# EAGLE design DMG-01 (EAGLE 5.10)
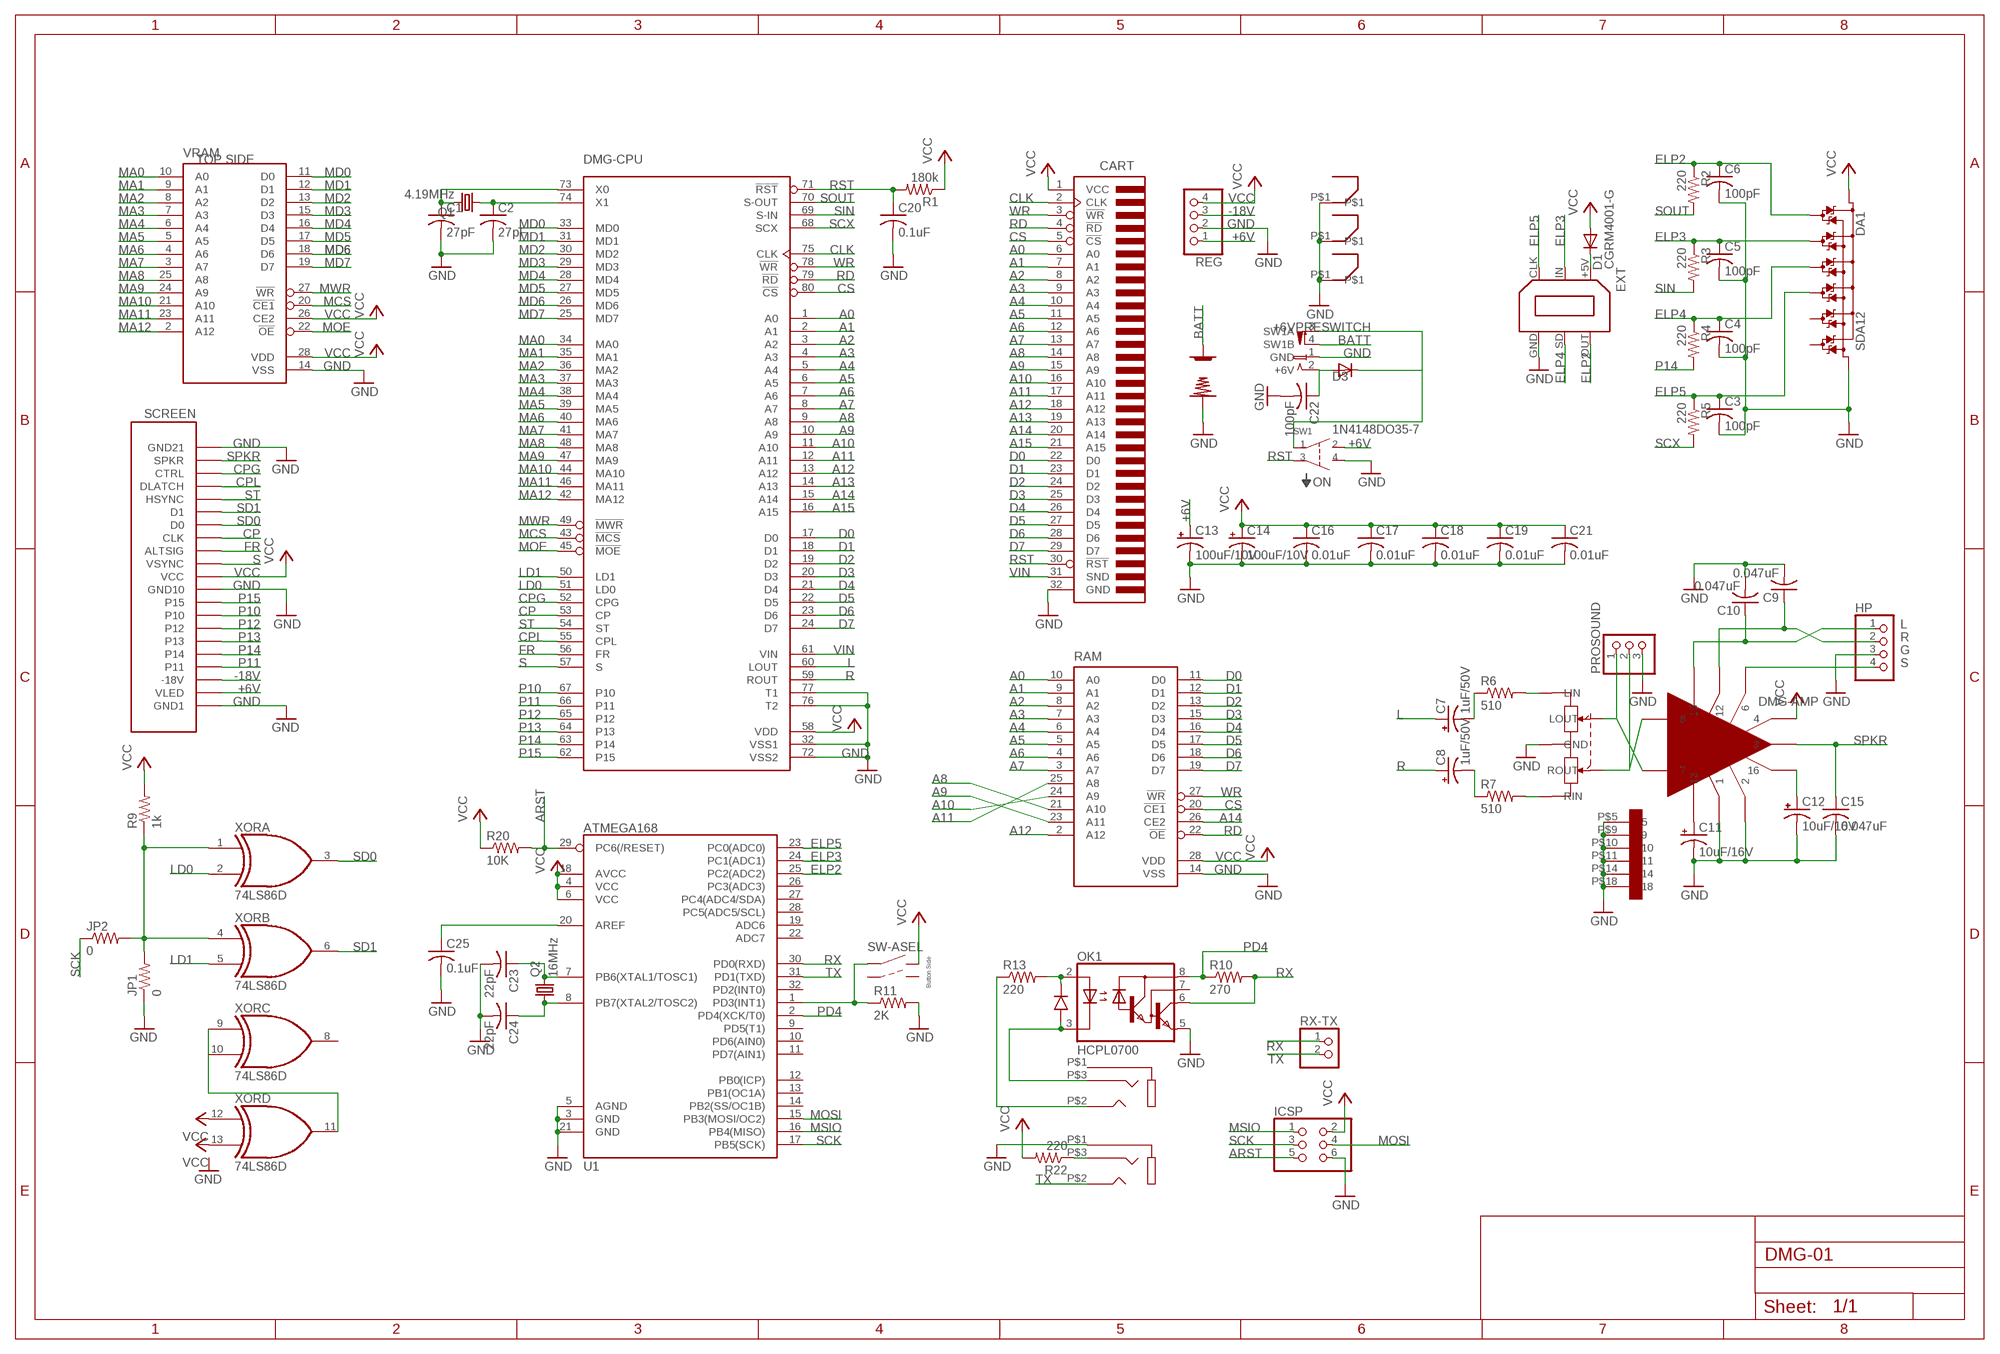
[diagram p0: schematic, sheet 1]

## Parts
+  DMG+BATTERY  [DMG+BATTERY]
-  DMG-BATTERY  [DMG-BATTERY]
C1  27pF  C0603  [R0603]
C2  27pF  C0603  [R0603]
C3  100pF  C0603  [R0603]
C4  100pF  C0603  [R0603]
C5  100pF  C0603  [R0603]
C6  100pF  C0603  [R0603]
C7  1uF/50V  C1206  [C1206]
C8  1uF/50V  C1206  [C1206]
C9  0.047uF  C0603  [R0603]
C10  0.047uF  C0603  [R0603]
C11  10uF/16V  C1206  [C1206]
C12  10uF/16V  C1206  [C1206]
C13  100uF/10V  C1206  [C1206]
C14  100uF/10V  C1206  [C1206]
C15  0.047uF  C0603  [R0603]
C16  0.01uF  C0603  [R0603]
C17  0.01uF  C0603  [R0603]
C18  0.01uF  C0603  [R0603]
C19  0.01uF  C0603  [R0603]
C20  0.1uF  C0603  [R0603]
C21  0.01uF  C0603  [R0603]
C22  100pF  C0603  [R0603]
C23  22pF  C0603  [R0603]
C24  22pF  C0603  [R0603]
C25  0.1uF  C0603  [R0603]
CART  GBCONN  [GBCONN]
D1  CGRM4001-G  [SOD-123_MINI-SMA]
D2  1N914  [SC-79]
D3  1N4148DO35-7  [DO35-7]
DA1  SDA12  [SO8]
DMG-AMP  DMG-AMP  [DMG-AMP]
DMG-CPU  DMG-CPU  [DMG-CPU]
EXT  LINKPORTDMG-LINK-SHORT  LINKPORTDMG-LINK  [DMG-LINK]
HP  PINHD-1X4OCT  [1X04OCT]
ICSP  PINHD-2X3  [2X03]
JP1  0  R0603  [R0603]
JP2  0  R0603  [R0603]
MIDIIN  SJ-3523  [SJ-3523]
MIDIOUT  SJ-3523  [SJ-3523]
OK1  HCPL0700  [SOIC08]
PROSOUND  PINHD-1X3OCT  [1X03OCT]
PWRJACK  DMG-PWRJACK  [DMG-PWRJACK]
Q1  4.19MHz  CRYSTALHC49S  [HC49/S]
Q2  16MHz  CRYSTALCTS406  [CTS406]
R1  180k  R0603  [R0603]
R2  220  R0603  [R0603]
R3  220  R0603  [R0603]
R4  220  R0603  [R0603]
R5  220  R0603  [R0603]
R6  510  R0603  [R0603]
R7  510  R0603  [R0603]
R9  1k  R0603  [R0603]
R10  270  R0603  [R0603]
R11  2K  R0603  [R0603]
R13  220  R0603  [R0603]
R20  10K  R0603  [R0603]
R22  220  R0603  [R0603]
RAM  LH5264  [SO28]
REG  PINHD-1X4OCT  [1X04OCT]
RX-TX  PINHD-1X2OCT  [1X02OCT]
SCREEN  DMG-SCREEN  DMG-SCREENCONNECTOR  [DMG-SCREEN]
SW1  DMG-SW  [DMG-SWITCH]
SW-ASEL  EVQ-PU  EVQ-PUNOGUIDE  [EVQ-PU2]
U1  ATMEGA168  [TQFP32-08]
U$1  DMG-CONTACT  [DMG-CONTACT]
U$2  DMG-CONTACT  [DMG-CONTACT]
U$3  DMG-CONTACT  [DMG-CONTACT]
VR1  10K  DMG-POT  [DMG-POT]
VRAM  LH5264  [SO28]
XOR  74LS86D  [SO14]

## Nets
+6V: C13.+ REG.1 SCREEN.P$2(VLED) SW1.P$2
+6VEXT: C22.1 D3.A PWRJACK.2(+6V)
+6VPRESWITCH: D3.C PWRJACK.3(SW1A) SW1.P$1
-18V: REG.3 SCREEN.P$3(-18V)
A0: CART.6(A0) DMG-CPU.1(A0) RAM.10(A0)
A1: CART.7(A1) DMG-CPU.2(A1) RAM.9(A1)
A2: CART.8(A2) DMG-CPU.3(A2) RAM.8(A2)
A3: CART.9(A3) DMG-CPU.4(A3) RAM.7(A3)
A4: CART.10(A4) DMG-CPU.5(A4) RAM.6(A4)
A5: CART.11(A5) DMG-CPU.6(A5) RAM.5(A5)
A6: CART.12(A6) DMG-CPU.7(A6) RAM.4(A6)
A7: CART.13(A7) DMG-CPU.8(A7) RAM.3(A7)
A8: CART.14(A8) DMG-CPU.9(A8) RAM.21(A10)
A9: CART.15(A9) DMG-CPU.10(A9) RAM.23(A11)
A10: CART.16(A10) DMG-CPU.11(A10) RAM.24(A9)
A11: CART.17(A11) DMG-CPU.12(A11) RAM.25(A8)
A12: CART.18(A12) DMG-CPU.13(A12) RAM.2(A12)
A13: CART.19(A13) DMG-CPU.14(A13)
A14: CART.20(A14) DMG-CPU.15(A14) RAM.26(CE2)
A15: CART.21(A15) DMG-CPU.16(A15)
ARST: ICSP.5 R20.2 U1.29(PC6(/RESET))
BATT: +.P$1 PWRJACK.4(SW1B)
CLK: CART.2(CLK) DMG-CPU.75(CLK)
CP: DMG-CPU.53(CP) SCREEN.P$14(CLK)
CPG: DMG-CPU.52(CPG) SCREEN.P$19(CTRL)
CPL: DMG-CPU.55(CPL) SCREEN.P$18(DLATCH)
CS: CART.5(!CS) DMG-CPU.80(!CS) RAM.20(!CE1)
D0: CART.22(D0) DMG-CPU.17(D0) RAM.11(D0)
D1: CART.23(D1) DMG-CPU.18(D1) RAM.12(D1)
D2: CART.24(D2) DMG-CPU.19(D2) RAM.13(D2)
D3: CART.25(D3) DMG-CPU.20(D3) RAM.15(D3)
D4: CART.26(D4) DMG-CPU.21(D4) RAM.16(D4)
D5: CART.27(D5) DMG-CPU.22(D5) RAM.17(D5)
D6: CART.28(D6) DMG-CPU.23(D6) RAM.18(D6)
D7: CART.29(D7) DMG-CPU.24(D7) RAM.19(D7)
ELP2: C6.1 DA1.2(D01) EXT.OUT R2.1 U1.25(PC2(ADC2))
ELP3: C5.1 DA1.3(D02) EXT.IN R3.1 U1.24(PC1(ADC1))
ELP4: C4.1 DA1.4(D03) EXT.SD R4.1
ELP5: C3.1 DA1.6(D04) EXT.CLK R5.1 U1.23(PC0(ADC0))
FR: DMG-CPU.56(FR) SCREEN.P$13(ALTSIG)
GND: -.P$1 C1.2 C2.2 C3.2 C4.2 C5.2 C6.2 C9.2 C10.2 C11.- C12.- C13.- C14.- C15.2 C16.2 C17.2 C18.2 C19.2 C20.2 C21.2 C22.2 C23.2 C24.2 C25.2 CART.32(GND) DA1.5(V-) DMG-AMP.P$1 DMG-AMP.P$2 DMG-AMP.P$5 DMG-AMP.P$9 DMG-AMP.P$10 DMG-AMP.P$11 DMG-AMP.P$14 DMG-AMP.P$18 DMG-CPU.32(VSS1) DMG-CPU.72(VSS2) DMG-CPU.76(T2) DMG-CPU.77(T1) EXT.GND HP.3 ICSP.6 JP1.1 MIDIOUT.P$1 OK1.5(GND) PROSOUND.3 PWRJACK.1(GND) R11.2 RAM.14(VSS) REG.2 SCREEN.P$1(GND1) SCREEN.P$10(GND10) SCREEN.P$21(GND21) SW1.P$4 U1.3(GND) U1.5(AGND) U1.21(GND) U$1.P$1 U$2.P$1 U$3.P$1 VR1.P$1(GND) VRAM.14(VSS)
L: C7.+ DMG-CPU.60(LOUT)
LD0: DMG-CPU.51(LD0) XOR.2(A:I1)
LD1: DMG-CPU.50(LD1) XOR.5(B:I1)
MA0: DMG-CPU.34(MA0) VRAM.10(A0)
MA1: DMG-CPU.35(MA1) VRAM.9(A1)
MA2: DMG-CPU.36(MA2) VRAM.8(A2)
MA3: DMG-CPU.37(MA3) VRAM.7(A3)
MA4: DMG-CPU.38(MA4) VRAM.6(A4)
MA5: DMG-CPU.39(MA5) VRAM.5(A5)
MA6: DMG-CPU.40(MA6) VRAM.4(A6)
MA7: DMG-CPU.41(MA7) VRAM.3(A7)
MA8: DMG-CPU.48(MA8) VRAM.25(A8)
MA9: DMG-CPU.47(MA9) VRAM.24(A9)
MA10: DMG-CPU.44(MA10) VRAM.21(A10)
MA11: DMG-CPU.46(MA11) VRAM.23(A11)
MA12: DMG-CPU.42(MA12) VRAM.2(A12)
MCS: DMG-CPU.43(!MCS) VRAM.20(!CE1)
MD0: DMG-CPU.33(MD0) VRAM.11(D0)
MD1: DMG-CPU.31(MD1) VRAM.12(D1)
MD2: DMG-CPU.30(MD2) VRAM.13(D2)
MD3: DMG-CPU.29(MD3) VRAM.15(D3)
MD4: DMG-CPU.28(MD4) VRAM.16(D4)
MD5: DMG-CPU.27(MD5) VRAM.17(D5)
MD6: DMG-CPU.26(MD6) VRAM.18(D6)
MD7: DMG-CPU.25(MD7) VRAM.19(D7)
MOE: DMG-CPU.45(!MOE) VRAM.22(!OE)
MOSI: ICSP.4 U1.15(PB3(MOSI/OC2))
MSIO: ICSP.1 U1.16(PB4(MISO))
MWR: DMG-CPU.49(!MWR) VRAM.27(!WR)
N$1: C11.+ DMG-AMP.P$13
N$2: C12.+ DMG-AMP.P$16
N$3: C10.1 DMG-AMP.P$15 HP.1
N$4: XOR.9(C:I0) XOR.10(C:I1) XOR.11(D:O)
N$10: JP1.2 JP2.2 R9.1 XOR.1(A:I0) XOR.4(B:I0)
N$13: R11.1 SW-ASEL.P$1 U1.1(PD3(INT1))
N$17: D1.C EXT.+5V
N$19: R6.2 VR1.P$4(LIN)
N$20: R7.2 VR1.P$5(RIN)
N$21: C7.- R6.1
N$22: C8.- R7.1
N$23: DMG-AMP.P$7 PROSOUND.1 VR1.P$3(LOUT)
N$24: DMG-AMP.P$8 PROSOUND.2 VR1.P$2(ROUT)
N$26: C9.1 DMG-AMP.P$12 HP.2
N$27: MIDIIN.P$2 R13.1
N$28: DMG-AMP.P$6 HP.4
N$31: D2.P$1 OK1.2(A) R13.2
N$32: C25.1 U1.20(AREF)
N$36: C23.1 Q2.3 U1.7(PB6(XTAL1/TOSC1))
N$37: C24.1 Q2.1 U1.8(PB7(XTAL2/TOSC2))
N$38: D2.P$2 MIDIIN.P$3 OK1.3(C)
N$40: MIDIOUT.P$3 R22.1
P10: DMG-CPU.67(P10) SCREEN.P$8(P10)
P11: DMG-CPU.66(P11) SCREEN.P$4(P11)
P12: DMG-CPU.65(P12) SCREEN.P$7(P12)
P13: DMG-CPU.64(P13) SCREEN.P$6(P13)
P14: DMG-CPU.63(P14) R4.2 SCREEN.P$5(P14)
P15: DMG-CPU.62(P15) SCREEN.P$9(P15)
PD4: OK1.8(VCC) R10.1 U1.2(PD4(XCK/T0))
R: C8.+ DMG-CPU.59(ROUT)
RD: CART.4(!RD) DMG-CPU.79(!RD) RAM.22(!OE)
RST: C20.1 CART.30(!RST) DMG-CPU.71(!RST) R1.2 SW1.P$3
RX: OK1.6(VO) R10.2 RX-TX.1 U1.30(PD0(RXD))
S: DMG-CPU.57(S) SCREEN.P$12(VSYNC)
SCK: ICSP.3 JP2.1 U1.17(PB5(SCK))
SCX: DMG-CPU.68(SCX) R5.2
SD0: SCREEN.P$15(D0) XOR.3(A:O)
SD1: SCREEN.P$16(D1) XOR.6(B:O)
SIN: DMG-CPU.69(S-IN) R3.2
SOUT: DMG-CPU.70(S-OUT) R2.2
SPKR: C15.1 DMG-AMP.P$3 SCREEN.P$20(SPKR)
ST: DMG-CPU.54(ST) SCREEN.P$17(HSYNC)
TX: MIDIOUT.P$2 RX-TX.2 U1.31(PD1(TXD))
VCC: C14.+ C16.1 C17.1 C18.1 C19.1 C21.1 CART.1(VCC) D1.A DA1.1(V+) DMG-AMP.P$4 DMG-CPU.58(VDD) ICSP.2 R1.1 R9.2 R20.1 R22.2 RAM.28(VDD) REG.4 SCREEN.P$11(VCC) SW-ASEL.P$2 U1.4(VCC) U1.6(VCC) U1.18(AVCC) VRAM.26(CE2) VRAM.28(VDD) XOR.12(D:I0) XOR.13(D:I1)
VIN: CART.31(SND) DMG-CPU.61(VIN)
WR: CART.3(!WR) DMG-CPU.78(!WR) RAM.27(!WR)
X0: C1.1 DMG-CPU.73(X0) Q1.2
X1: C2.1 DMG-CPU.74(X1) Q1.1
Unconnected: DA1.7(D05) DA1.8(D06) MIDIIN.P$1 OK1.7(VB) SW-ASEL.P$3 SW-ASEL.P$4 U1.9(PD5(T1)) U1.10(PD6(AIN0)) U1.11(PD7(AIN1)) U1.12(PB0(ICP)) U1.13(PB1(OC1A)) U1.14(PB2(SS/OC1B)) U1.19(ADC6) U1.22(ADC7) U1.26(PC3(ADC3)) U1.27(PC4(ADC4/SDA)) U1.28(PC5(ADC5/SCL)) U1.32(PD2(INT0)) XOR.8(C:O)

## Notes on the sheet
- TOP SIDE
- L
- R
- G
- S

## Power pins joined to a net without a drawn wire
GND: XOR.7(P:GND)
VCC: XOR.14(P:VCC)

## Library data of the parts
+ = Game Boy:DMG+BATTERY
- = Game Boy:DMG-BATTERY
C1-C6 C9 C10 C15-C25 = Game Boy:C0603
C7 C8 C11-C14 = Game Boy:C1206
CART = GameboyDev:GBCONN
D1 = diode:CGRM400*-G: Molded plasitc,JEDEC SOD-123/Mini SMA
D2 = Game Boy:1N914
D3 = diode:1N4148: DIODE
DA1 = zetex:SDA12: DIODE ARRAY
DMG-AMP = Game Boy:DMG-AMP
DMG-CPU = Game Boy:DMG-CPU
EXT = Game Boy:LINKPORT
HP REG = pinhead:PINHD-1X4: PIN HEADER
ICSP = pinhead:PINHD-2X3: PIN HEADER
JP1 JP2 R1-R7 R9-R11 R13 R20 R22 = Game Boy:R0603
MIDIIN MIDIOUT = Game Boy:SJ-3523
OK1 = optocoupler:HCPL0700: HEWLETT PACKARD OPTO COUPLER
PROSOUND = header:PINHD-1X3: PIN HEADER
PWRJACK = Game Boy:DMG-PWRJACK
Q1 Q2 = crystal:CRYSTAL: CRYSTAL
RAM VRAM = Game Boy:LH5264
RX-TX = pinhead:PINHD-1X2: PIN HEADER
SCREEN = Game Boy:DMG-SCREEN: The white connector for the ribbon cable to connect the DMG's front half
SW1 = Game Boy:DMG-SW: DMG Power Switch Pins 1 and 2 are only connected when the power is ON, pins 3 and 4 are only connected when the power is OFF.
SW-ASEL = Game Boy:EVQ-PU
U1 = SparkFun:ATMEGA168
U$1-U$3 = Game Boy:DMG-CONTACT
VR1 = Game Boy:DMG-POT
XOR = 74xx-us:74*86: Quad 2-input EXCLUSIV-OR (XOR) gate

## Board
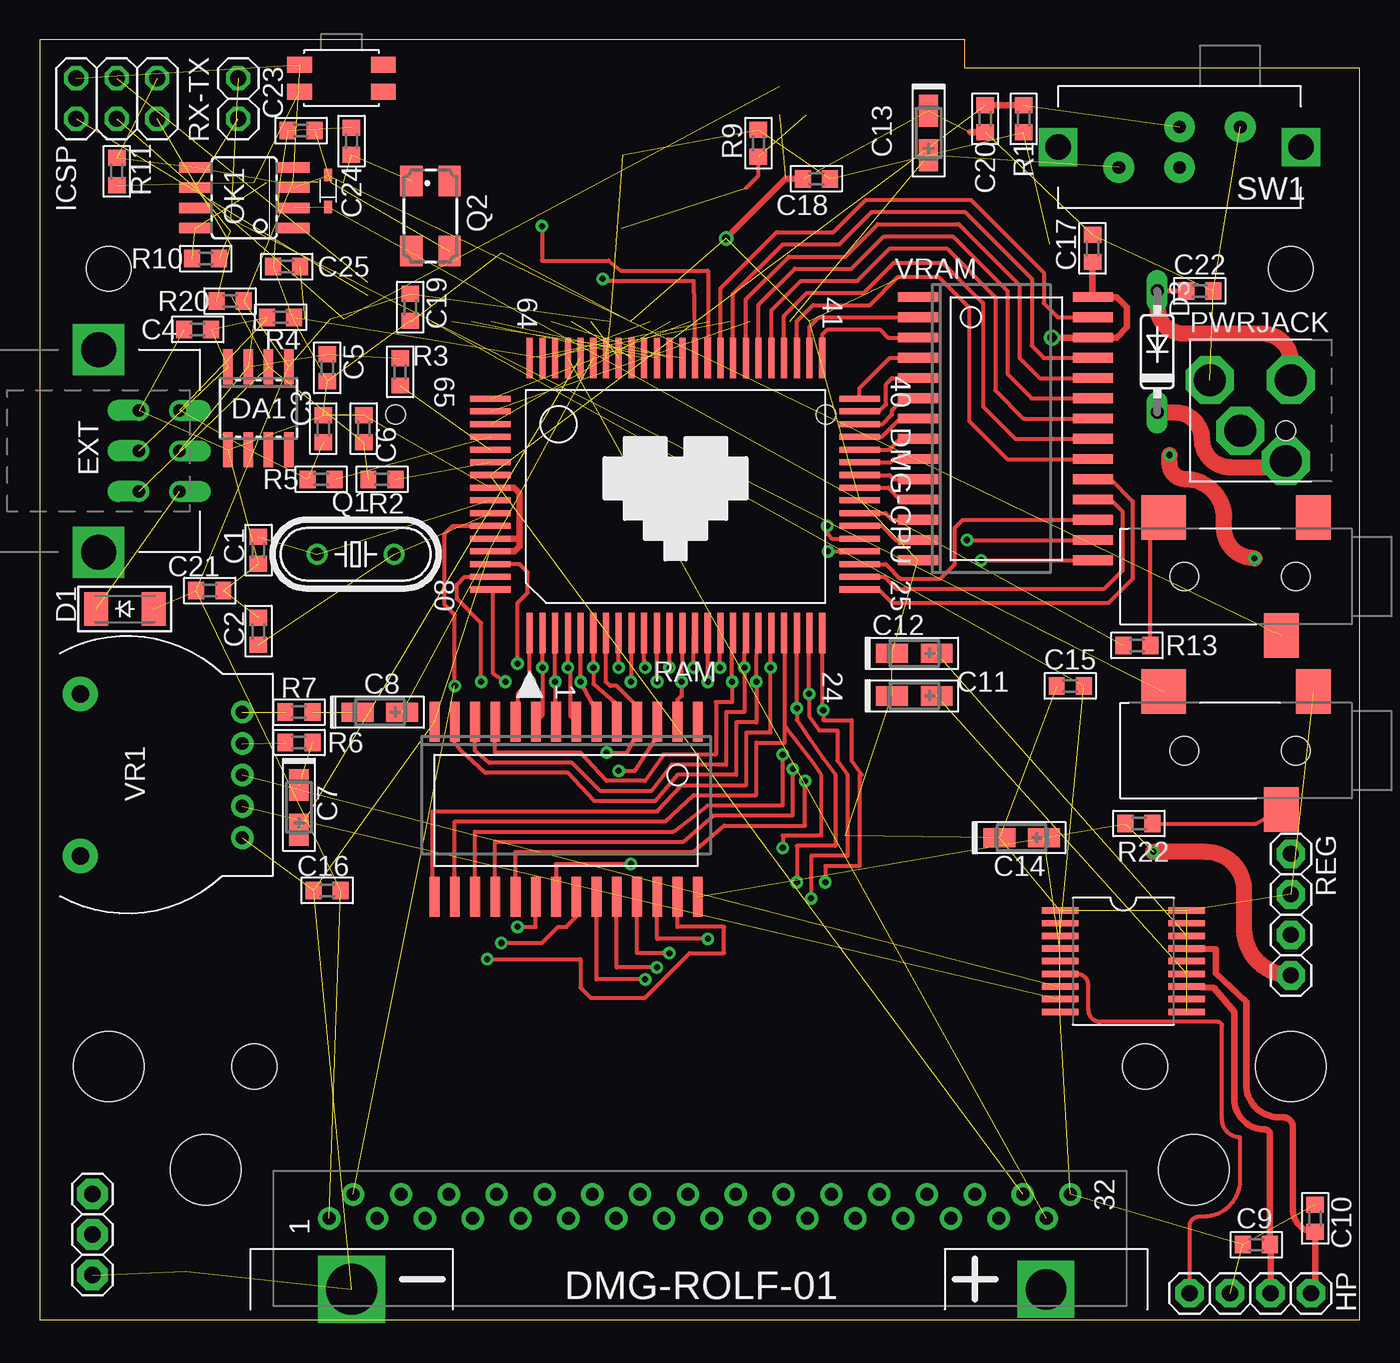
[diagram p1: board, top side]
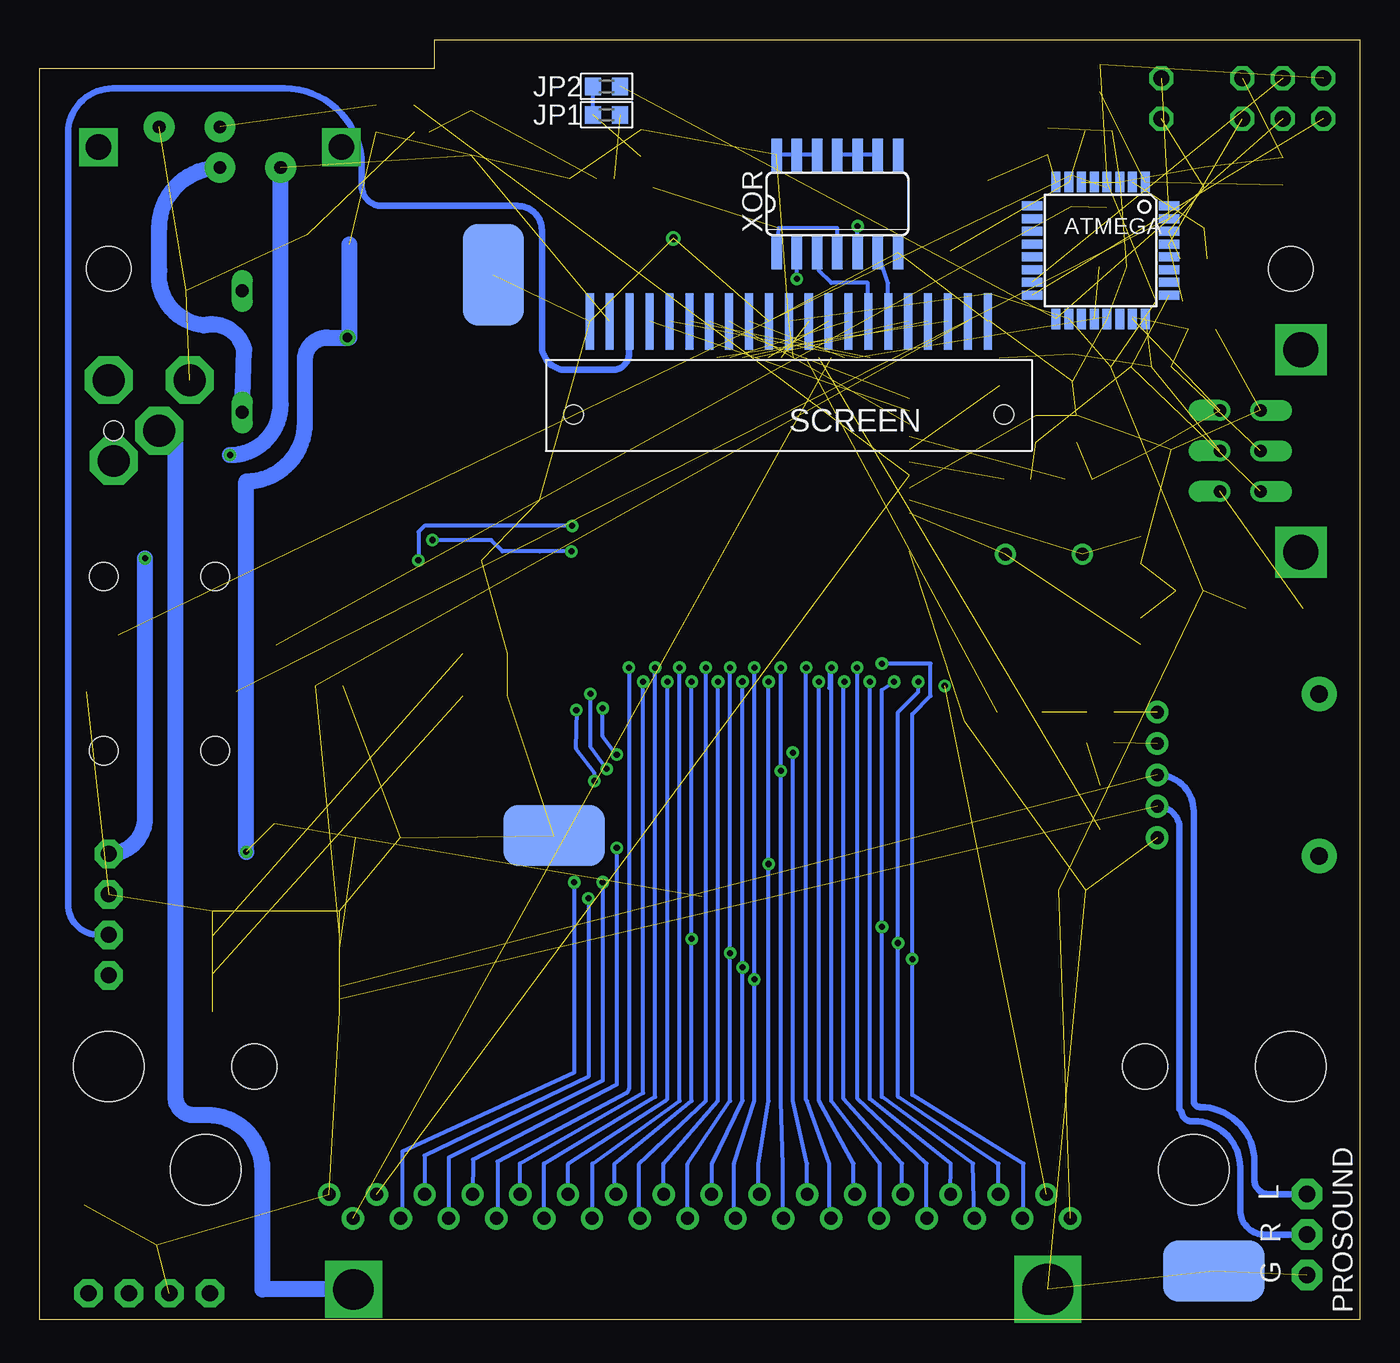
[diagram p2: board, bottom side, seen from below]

Size 82.8 x 80.26 mm. Coordinates in mm from the lower left corner, seen from the top.
Outline: 0,0 82.8,0 82.8,78.49 58.04,78.49 58.04,80.26 0,80.26 0,0
Copper layers (1*16): Top 0.035mm / dielectric 1.5mm / Bottom 0.035mm
Design rules "default *": minimum track width 10mil, minimum drill 15mil, track to track 8mil, track to pad 8mil, pad to pad 8mil, via to via 8mil, smd to smd 8mil, copper to edge 20mil, drill to drill 15mil, minimum pad ring 10mil, minimum via ring 8mil, stop-mask expansion 4mil, vias tented up to drill 0mil, thermal gap 10mil
Holes 2.8 mm at 4.32,65.91 78.49,65.91 13.46,15.88 69.34,15.88
Holes 4.41 mm at 10.41,9.4 72.39,9.4 4.32,15.88 78.49,15.88
tKeepout: area 0.3,61.8 to 8.4,70; area 74.4,61.8 to 82.6,70

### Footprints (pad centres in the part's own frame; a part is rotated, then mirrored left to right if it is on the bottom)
DMG+BATTERY = drill 2.54 square: P$1 0,0
DMG-BATTERY = drill 3.2 square: P$1 0,0
R0603 = smd 1 x 1.1: 1 -0.85,0; 2 0.85,0
C1206 = smd 2 x 1.2: + -1.4,0; - 1.4,0
GBCONN = drill 0.813 pad 1.397 round: 1 0,0; 2 -1.5,1.5; 3 0,3; 4 -1.5,4.5; 5 0,6; 6 -1.5,7.5; 7 0,9; 8 -1.5,10.5; 9 0,12; 10 -1.5,13.5; 11 0,15; 12 -1.5,16.5; 13 0,18; 14 -1.5,19.5; 15 0,21; 16 -1.5,22.5; 17 0,24; 18 -1.5,25.5; 19 0,27; 20 -1.5,28.5; 21 0,30; 22 -1.5,31.5; 23 0,33; 24 -1.5,34.5; 25 0,36; 26 -1.5,37.5; 27 0,39; 28 -1.5,40.5; 29 0,42; 30 -1.5,43.5; 31 0,45; 32 -1.5,46.5
SOD-123_MINI-SMA = smd 1.5 x 2.1: A 1.8,0; C -1.8,0
SC-79 = smd 0.5 x 0.8: P$1 0,1; P$2 0,-1
DO35-7 = drill 0.813 long: A 3.81,0; C -3.81,0
SO8 = smd 0.6 x 2.2: 1 -1.905,-2.6; 2 -0.635,-2.6; 3 0.635,-2.6; 4 1.905,-2.6; 5 1.905,2.6; 6 0.635,2.6; 7 -0.635,2.6; 8 -1.905,2.6
DMG-AMP = smd 0.406 x 2.286: P$1 0,0; P$2 0.794,0; P$3 1.587,0; P$4 2.381,0; P$5 3.175,0; P$6 3.969,0; P$7 4.763,0; P$8 5.556,0; P$9 6.35,0; P$10 6.35,7.938; P$11 5.556,7.938; P$12 4.763,7.938; P$13 3.969,7.938; P$14 3.175,7.938; P$15 2.381,7.938; P$16 1.587,7.938; P$17 0.794,7.938; P$18 0,7.938
DMG-CPU = smd 0.381 x 2.54: 1 -8.89,-8.255; 2 -8.092,-8.255; 3 -7.294,-8.255; 4 -6.496,-8.255; 5 -5.698,-8.255; 6 -4.901,-8.255; 7 -4.103,-8.255; 8 -3.305,-8.255; 9 -2.507,-8.255; 10 -1.709,-8.255; 11 -0.911,-8.255; 12 -0.113,-8.255; 13 0.685,-8.255; 14 1.483,-8.255; 15 2.28,-8.255; 16 3.078,-8.255; 17 3.876,-8.255; 18 4.674,-8.255; 19 5.472,-8.255; 20 6.27,-8.255; 21 7.068,-8.255; 22 7.866,-8.255; 23 8.664,-8.255; 24 9.461,-8.255; 41 9.461,9.009; 42 8.664,9.009; 43 7.866,9.009; 44 7.068,9.009; 45 6.27,9.009; 46 5.472,9.009; 47 4.674,9.009; 48 3.876,9.009; 49 3.078,9.009; 50 2.28,9.009; 51 1.483,9.009; 52 0.685,9.009; 53 -0.113,9.009; 54 -0.911,9.009; 55 -1.709,9.009; 56 -2.507,9.009; 57 -3.305,9.009; 58 -4.103,9.009; 59 -4.901,9.009; 60 -5.698,9.009; 61 -6.496,9.009; 62 -7.294,9.009; 63 -8.092,9.009; 64 -8.89,9.009 | smd 2.54 x 0.381: 25 11.819,-5.516; 26 11.819,-4.718; 27 11.819,-3.92; 28 11.819,-3.123; 29 11.819,-2.325; 30 11.819,-1.527; 31 11.819,-0.729; 32 11.819,0.069; 33 11.819,0.867; 34 11.819,1.665; 35 11.819,2.463; 36 11.819,3.261; 37 11.819,4.059; 38 11.819,4.856; 39 11.819,5.654; 40 11.819,6.452; 65 -11.375,6.452; 66 -11.375,5.654; 67 -11.375,4.856; 68 -11.375,4.058; 69 -11.375,3.26; 70 -11.375,2.463; 71 -11.375,1.665; 72 -11.375,0.867; 73 -11.375,0.069; 74 -11.375,-0.729; 75 -11.375,-1.527; 76 -11.375,-2.325; 77 -11.375,-3.123; 78 -11.375,-3.921; 79 -11.375,-4.718; 80 -11.375,-5.516
DMG-LINK = drill 0.8 offset: +5V 2.54,5.08; CLK -2.54,5.08; GND -2.54,2.54; IN 0,5.08; OUT 2.54,2.54; SD 0,2.54 | drill 2.2 square: SHIELD -6.35,0; SHIELD1 6.35,0
1X04OCT = drill 1.016 pad 1.778 octagon: 1 -3.81,0; 2 -1.27,0; 3 1.27,0; 4 3.81,0
2X03 = drill 1.016 octagon: 1 -2.54,-1.27; 2 -2.54,1.27; 3 0,-1.27; 4 0,1.27; 5 2.54,-1.27; 6 2.54,1.27
SJ-3523 = smd 2.2 x 2.8: P$1 -2.4,3.7; P$3 -4.4,-3.7 | smd 2.8 x 2.8: P$2 -11.8,3.7 | hole 1.778: -3.5,0; -10.5,0
SOIC08 = smd 0.66 x 2.032: 1 -1.905,-3.073; 2 -0.635,-3.073; 3 0.635,-3.073; 4 1.905,-3.073; 5 1.905,3.073; 6 0.635,3.073; 7 -0.635,3.073; 8 -1.905,3.073
1X03OCT = drill 1.016 pad 1.93 octagon: 1 -2.54,0; 2 0,0; 3 2.54,0
DMG-PWRJACK = drill 2 octagon: 1 -2.54,0; 2 2.54,0; 3 2.223,-5.08; 4 -0.635,-3.175 | hole 1.2: 2.223,-3.175
HC49/S = drill 0.813 round: 1 -2.413,0; 2 2.413,0
CTS406 = smd 1.9 x 1.4: 1 -2.2,-1.2; 2 2.2,-1.2; 3 2.2,1.2; 4 -2.2,1.2
SO28 = smd 0.6 x 2.5: 1 -8.255,-4.6; 2 -6.985,-4.6; 3 -5.715,-4.6; 4 -4.445,-4.6; 5 -3.175,-4.6; 6 -1.905,-4.6; 7 -0.635,-4.6; 8 0.635,-4.6; 9 1.905,-4.6; 10 3.175,-4.6; 11 4.445,-4.6; 12 5.715,-4.6; 13 6.985,-4.6; 14 8.255,-4.6; 15 8.255,6.378; 16 6.985,6.378; 17 5.715,6.378; 18 4.445,6.378; 19 3.175,6.378; 20 1.905,6.378; 21 0.635,6.378; 22 -0.635,6.378; 23 -1.905,6.378; 24 -3.175,6.378; 25 -4.445,6.378; 26 -5.715,6.378; 27 -6.985,6.378; 28 -8.255,6.378
1X02OCT = drill 1.016 octagon: 1 -1.27,0; 2 1.27,0
DMG-SCREEN = smd 0.508 x 3.556: P$1 -12.484,3.745; P$2 -11.236,3.745; P$3 -9.987,3.745; P$4 -8.739,3.745; P$5 -7.49,3.745; P$6 -6.242,3.745; P$7 -4.994,3.745; P$8 -3.745,3.745; P$9 -2.497,3.745; P$10 -1.248,3.745; P$11 0,3.745; P$12 1.248,3.745; P$13 2.497,3.745; P$14 3.745,3.745; P$15 4.994,3.745; P$16 6.242,3.745; P$17 7.49,3.745; P$18 8.739,3.745; P$19 9.987,3.745; P$20 11.236,3.745; P$21 12.484,3.745 | hole 1.2: -13.5,-2.097; 13.5,-2.097
DMG-SWITCH = drill 0.8 pad 1.93 round: P$1 0,-1.27; P$2 -3.81,-1.27; P$3 0,1.27; P$4 3.81,1.27 | drill 1.6 square: P$7 -7.62,0; P$8 7.62,0
EVQ-PU2 = smd 1.55 x 1: P$1 2.625,0.85; P$2 2.625,-0.85; P$3 -2.625,0.85; P$4 -2.625,-0.85
TQFP32-08 = smd 1.27 x 0.559: 1 -4.293,2.8; 2 -4.293,2; 3 -4.293,1.2; 4 -4.293,0.4; 5 -4.293,-0.4; 6 -4.293,-1.2; 7 -4.293,-2; 8 -4.293,-2.8; 17 4.293,-2.8; 18 4.293,-2; 19 4.293,-1.2; 20 4.293,-0.4; 21 4.293,0.4; 22 4.293,1.2; 23 4.293,2; 24 4.293,2.8 | smd 0.559 x 1.27: 9 -2.8,-4.293; 10 -2,-4.293; 11 -1.2,-4.293; 12 -0.4,-4.293; 13 0.4,-4.293; 14 1.2,-4.293; 15 2,-4.293; 16 2.8,-4.293; 25 2.8,4.293; 26 2,4.293; 27 1.2,4.293; 28 0.4,4.293; 29 -0.4,4.293; 30 -1.2,4.293; 31 -2,4.293; 32 -2.8,4.293
DMG-CONTACT = smd 3.81 x 6.35: P$1 0,0
DMG-POT = drill 0.8 pad 1.422 round: P$1 -3.937,-5.08; P$2 -1.968,-5.08; P$3 0,-5.08; P$4 1.968,-5.08; P$5 3.937,-5.08 | drill 1.1 pad 2.184 round: P$6 -5.08,5.08; P$7 5.08,5.08
SO14 = smd 0.66 x 2.032: 1 -3.81,-3.073; 2 -2.54,-3.073; 3 -1.27,-3.073; 4 0,-3.073; 5 1.27,-3.073; 6 2.54,-3.073; 7 3.81,-3.073; 8 3.81,3.073; 9 2.54,3.073; 10 1.27,3.073; 11 0,3.073; 12 -1.27,3.073; 13 -2.54,3.073; 14 -3.81,3.073

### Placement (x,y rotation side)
+  63.12,1.91 0 top
-  19.56,1.91 0 top
C1  13.72,48.26 270 top
C2  13.72,43.18 90 top
C3  17.78,55.88 90 top
C4  9.91,62.1 180 top
C5  18.03,59.69 270 top
C6  20.32,55.88 90 top
C7  16.26,32.13 90 top
C8  21.34,38.1 180 top
C9  76.33,4.7 180 top
C10  80.01,6.35 90 top
C11  54.86,39.12 180 top
C12  54.86,41.78 180 top
C13  55.75,74.42 90 top
C14  61.59,30.23 180 top
C15  64.64,39.75 180 top
C16  18.03,26.92 180 top
C17  66.04,67.18 90 top
C18  48.72,71.55 180 top
C19  23.24,63.5 270 top
C20  59.31,75.31 270 top
C21  10.67,45.72 0 top
C22  72.77,64.52 0 top
C23  16.38,74.57 180 top
C24  19.56,73.91 90 top
C25  15.49,66.04 180 top
CART  18.16,6.35 270 top
D1  5.33,44.58 0 top
D2  18.08,70.78 180 top
D3  70.1,60.71 90 top
DA1  13.72,57.15 180 top
DMG-AMP  64.01,25.65 270 top
DMG-CPU  39.62,51.31 0 top
EXT  3.68,54.48 270 top
HP  75.95,1.65 180 top
ICSP  4.83,76.58 0 top
JP1  47.24,75.56 180 bottom
JP2  47.24,77.34 180 bottom
MIDIIN  82.3,46.61 0 top
MIDIOUT  82.3,35.69 0 top
OK1  12.83,70.36 90 top
PROSOUND  3.3,5.33 270 top
PWRJACK  75.95,58.93 0 top
Q1  19.81,48.01 180 top
Q2  24.51,69.22 270 top
R1  61.72,75.31 90 top
R2  21.46,52.7 0 top
R3  22.61,59.44 270 top
R4  15.11,62.87 0 top
R5  17.65,52.7 0 top
R6  16.26,36.2 180 top
R7  16.26,38.1 180 top
R9  45.09,73.79 90 top
R10  10.41,66.55 0 top
R11  4.83,72.01 90 top
R13  68.83,42.29 180 top
R20  11.94,63.88 180 top
R22  68.96,31.11 180 top
RAM  33.02,32.89 180 top
REG  78.49,25.4 270 top
RX-TX  12.45,76.58 90 top
SCREEN  35.81,58.86 0 bottom
SW1  71.5,73.53 0 top
SW-ASEL  18.92,77.85 180 top
U1  16.26,67.06 270 bottom
U$1  54.36,65.53 180 bottom
U$2  50.55,30.35 270 bottom
U$3  9.14,3.05 270 bottom
VR1  7.62,34.16 90 top
VRAM  59.69,55.88 270 top
XOR  32.77,69.98 0 bottom

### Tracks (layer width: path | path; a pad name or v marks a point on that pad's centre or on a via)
+6V  (via drill 0.38 pad 0.25)  (2 unrouted)
  Top 1.016: v70.87,54.23 70.87,53.72 arc90 71.88,52.7 arc-90 74.3,50.29 74.3,49.66 arc90 v76.2,47.75
  Bottom 1.016: SW1.P$2 67.69,57.4 arc90 v70.87,54.23 | v76.2,47.75 76.2,31.5 arc90 REG.1
+6VEXT
  Top 0.305: D3.A C22.1
  Top 1.016: PWRJACK.2 78.49,60.07 arc90 76.71,61.85 71.75,61.85 arc-90 70.1,63.5 D3.A
+6VPRESWITCH
  Top 1.016: PWRJACK.3 arc-90 77.79,53.47 74.68,53.47 arc-90 72.9,55.24 arc90 71.25,56.9 D3.C
  Bottom 1.016: D3.C 69.98,60.83 arc-90 72.52,62.36 arc90 75.31,65.79 75.31,68.45 arc90 SW1.P$1
-18V
  Bottom 0.406: REG.3 79.12,24.13 arc90 81.03,26.04 81.03,74.42 arc90 78.23,77.22 67.44,77.22 arc90 62.61,72.39 62.61,71.12 arc-90 61.34,69.85 52.83,69.85 arc90 51.31,68.33 51.31,61.09 arc-90 49.78,59.56 46.86,59.56 arc-90 45.85,60.58 45.85,62.56 arc90 SCREEN.P$3
A0  (via drill 0.38)
  Top 0.254: DMG-CPU.1 v30.73,40.01 29.97,39.24 29.97,37.62 RAM.10
  Bottom 0.254: CART.6 25.65,9.78 30.73,13.84 v30.73,40.01
A1  (via drill 0.38)
  Top 0.254: DMG-CPU.2 v31.53,40.89 31.53,37.91 RAM.9
  Bottom 0.254: CART.7 27.18,6.35 27.18,9.78 31.5,13.84 31.5,40.89 v31.53,40.89
A2  (via drill 0.38)
  Top 0.254: DMG-CPU.3 v32.33,40.01 32.33,37.55 RAM.8
  Bottom 0.254: CART.8 28.7,7.85 28.7,9.78 32.38,13.84 32.38,40.01 v32.33,40.01
A3  (via drill 0.38)
  Top 0.254: DMG-CPU.4 v33.13,40.89 33.27,40.75 33.27,37.87 RAM.7
  Bottom 0.254: 33.27,39.62 33.27,40.75 v33.13,40.89 33.15,40.89 33.15,13.72 30.1,9.78 30.1,6.35 CART.9
A4  (via drill 0.38)  (1 unrouted)
  Top 0.254: DMG-CPU.5 v33.93,40.01 34.92,38.12 RAM.6
  Bottom 0.254: CART.10 31.75,7.85 31.75,9.78 33.91,13.72 33.91,40.01
A5  (via drill 0.38)
  Top 0.254: DMG-CPU.6 v34.72,40.89 34.72,39.88 35.31,39.37 36.07,38.73 RAM.5
  Bottom 0.254: CART.11 33.27,6.35 33.27,9.78 34.67,13.72 34.72,13.77 v34.72,40.89
A6  (via drill 0.38 pad 0.25)
  Top 0.254: DMG-CPU.7 35.52,40.01 35.77,39.75 36.2,39.75 37.47,38.48 RAM.4 | RAM.4 37.59,37.37 | v35.56,35.56 36.83,35.56 37.47,36.7 RAM.4
  Bottom 0.254: CART.12 34.67,9.78 35.56,13.72 v35.56,35.56
A7  (via drill 0.38, 0.38 pad 0.25)
  Top 0.254: v36.32,40.89 DMG-CPU.8 | v36.32,34.42 37.34,34.42 38.73,36.58 RAM.3
  Bottom 0.254: CART.13 36.2,6.35 36.2,9.65 | 36.2,9.65 36.2,9.78 | 36.32,13.72 v36.32,34.42 v36.32,40.89 | 36.32,13.72 | 36.2,9.65 36.32,13.72
A8  (via drill 0.38, 0.38 pad 0.25)
  Top 0.254: DMG-CPU.9 37.12,40.23 v37.08,40.01 | RAM.21 32.38,28.57 v37.08,28.57
  Bottom 0.254: CART.14 37.72,7.85 37.72,9.78 37.08,13.72 37.08,28.19 v37.08,28.57 v37.08,40.01
A9  (via drill 0.38, 0.38 pad 0.25)
  Top 0.254: DMG-CPU.10 37.91,41.33 v37.97,40.89 | RAM.23 34.92,21.34 v37.97,21.34
  Bottom 0.254: CART.15 39.24,6.35 39.24,9.78 37.97,13.72 v37.97,21.34 | v37.97,21.34 v37.97,40.89 | v37.97,21.34 37.97,21.59
A10  (via drill 0.38, 0.38 pad 0.25)
  Top 0.254: v38.73,40.01 v38.71,40.03 DMG-CPU.11 | RAM.24 36.2,22.1 v38.71,22.1
  Bottom 0.254: CART.16 40.64,7.85 40.64,9.78 38.73,13.72 38.71,13.74 v38.71,22.1 v38.71,40.03
A11  (via drill 0.38, 0.38 pad 0.25)
  Top 0.254: DMG-CPU.12 39.51,41.01 39.5,40.99 v39.5,40.89 | RAM.25 37.47,22.99 v39.5,22.99
  Bottom 0.254: CART.17 42.16,9.78 39.5,13.72 v39.5,22.99 | v39.5,22.99 v39.5,40.89 | v39.5,22.99 39.5,23.11
A12  (via drill 0.38 pad 0.25)
  Top 0.254: DMG-CPU.13 40.31,41.1 40.26,41.05 v40.26,40.01 40.26,39.12 40.01,38.86 RAM.2
  Bottom 0.254: v40.26,40.01 40.26,13.72 43.69,9.78 43.69,7.85 CART.18
A13  (via drill 0.38 pad 0.25)
  Top 0.254: v41.02,40.89 41.02,42.97 DMG-CPU.14
  Bottom 0.254: v41.02,40.89 41.02,13.72 45.21,9.78 45.21,6.35 CART.19
A14  (via drill 0.38 pad 0.25)
  Top 0.254: v41.91,40.01 DMG-CPU.15 | RAM.26 38.73,23.88 v41.91,23.88
  Bottom 0.254: v41.91,40.01 v41.91,23.88 41.91,13.72 46.74,9.78 46.74,7.85 CART.20
A15  (via drill 0.38 pad 0.25)
  Top 0.254: v42.67,40.89 DMG-CPU.16
  Bottom 0.254: v42.67,40.89 42.67,13.72 48.13,9.78 48.13,6.35 CART.21
ARST  (2 unrouted)
BATT
  Bottom 1.016: +.P$1 68.83,1.91 68.83,9.4 arc-90 72.26,12.83 73.15,12.83 arc90 74.3,13.97 74.3,54.74 arc-90 PWRJACK.4
CLK  (via drill 0.38)  (1 unrouted)
  Top 0.254: DMG-CPU.75 25.91,49.78 25.4,49.28 25.4,44.83 26.04,44.2 v26.04,39.75
CP  (1 unrouted)
CPG  (1 unrouted)
CPL  (1 unrouted)
CS  (via drill 0.38 pad 0.25)
  Top 0.254: v29.21,40.01 28.45,40.51 28.45,45.59 DMG-CPU.80 | RAM.20 31.11,24.64 v29.97,24.64
  Bottom 0.254: v29.21,40.01 29.97,39.5 29.97,24.77 v29.97,24.64 29.97,13.97 24.26,9.78 CART.5
D0  (via drill 0.38 pad 0.25)
  Top 0.254: DMG-CPU.17 43.43,41.66 v43.43,40.01 43.43,38.73 42.42,38.73 42.42,35.43 39.12,35.43 37.97,33.78 35.56,33.78 33.91,35.56 28.57,35.56 RAM.11
  Bottom 0.254: CART.22 49.66,9.78 43.56,13.72 43.43,13.84 v43.43,40.01
D1  (via drill 0.38 pad 0.25)
  Top 0.254: DMG-CPU.18 44.2,41.66 v44.2,40.89 44.2,38.1 43.05,38.1 43.05,34.8 39.62,34.8 38.35,33.15 35.18,33.15 33.4,34.92 28.19,34.92 27.3,35.69 RAM.12
  Bottom 0.254: CART.23 51.18,9.78 44.2,13.97 v44.2,40.89
D2  (via drill 0.38 pad 0.25)
  Top 0.254: DMG-CPU.19 44.96,41.53 v44.96,40.01 44.96,37.47 43.69,37.47 43.69,34.16 40.01,34.16 38.61,32.51 34.8,32.51 33.15,34.29 27.94,34.29 26.42,35.69 26.04,36.2 RAM.13
  Bottom 0.254: CART.24 52.7,7.87 52.7,9.78 44.96,14.22 v44.96,40.01
D3  (via drill 0.38 pad 0.25)
  Top 0.254: DMG-CPU.20 45.85,41.4 v45.85,40.89 45.85,36.83 44.32,36.83 44.32,33.53 40.26,33.53 38.73,31.88 24.64,31.88 24.64,26.64 RAM.15
  Bottom 0.254: CART.25 54.1,6.35 54.1,9.91 45.97,14.22 45.85,14.48 v45.85,40.89
D4  (via drill 0.38 pad 0.25)
  Top 0.254: RAM.16 26.04,31.24 39.24,31.24 41.02,32.89 44.96,32.89 44.96,36.2 46.74,36.2 46.74,37.08 | v46.61,29.59 46.61,30.35 49.02,30.35 49.02,34.16 48.51,34.92 46.82,37.13 46.77,37.08 46.74,37.08 | 46.74,37.08 46.74,43.01 DMG-CPU.21
  Bottom 0.254: v46.61,29.59 46.61,14.73 55.63,10.03 CART.26
D5  (via drill 0.38 pad 0.25)
  Top 0.254: v47.5,38.35 DMG-CPU.22 | RAM.17 27.3,30.61 39.75,30.61 41.91,32.26 46.61,32.26 v46.61,35.43 | v47.5,38.35 47.5,37.59 48.64,35.94 49.15,35.18 49.91,34.16 49.91,29.72 47.5,29.72 v47.5,27.43 | v47.5,38.35 47.5,38.23
  Bottom 0.254: v46.61,35.43 47.5,36.58 47.5,38.48 v47.5,38.35 | v47.5,27.43 47.5,14.99 57.15,10.16 CART.27
D6  (via drill 0.38 pad 0.25)
  Top 0.254: RAM.18 28.57,29.97 40.39,29.97 42.29,31.62 47.24,31.62 v47.24,34.54 | DMG-CPU.23 48.26,43.05 v48.26,39.24 48.26,37.85 48.9,36.96 50.04,36.96 50.04,35.05 50.67,34.16 50.67,29.08 48.39,29.08 v48.39,26.42
  Bottom 0.254: v47.24,34.54 48.26,35.94 v48.26,39.24 | CART.28 58.67,10.29 48.39,15.24 v48.39,26.42
D7  (via drill 0.38 pad 0.25)
  Top 0.254: RAM.19 29.84,29.34 41.02,29.34 42.93,30.99 48.01,30.99 v48.01,33.78 | v49.28,27.43 49.28,28.45 51.44,28.45 51.44,34.16 51.56,34.16 50.93,35.05 50.93,37.59 49.15,37.59 v49.15,38.23 arc-90 49.09,38.29 DMG-CPU.24
  Bottom 0.254: v48.01,33.78 48.01,34.29 49.15,35.81 49.09,38.23 v49.15,38.23 | CART.29 60.07,6.35 60.07,10.54 49.28,15.49 v49.28,27.43
ELP2  (4 unrouted)
ELP3  (4 unrouted)
ELP4  (3 unrouted)
ELP5  (4 unrouted)
FR  (1 unrouted)
GND  (via drill 0.5)  (59 unrouted)
  Top 0.406: C13.- | 58.38,74.46 C20.2 | DMG-CPU.72 29.74,52.17 30.1,51.82 30.1,49.02 | v43.05,67.82 46.79,71.55 C18.2 | DMG-CPU.77 29.77,48.19 30.1,48.51 30.1,49.02 | DMG-CPU.76 30.06,48.98 30.1,49.02
L  (1 unrouted)
LD0  (via drill 0.38 pad 0.25)
  Top 0.254: DMG-CPU.51 41.02,65.15 35.31,65.15 v35.31,65.28
  Bottom 0.254: v35.31,65.28 XOR.2
LD1  (via drill 0.38 pad 0.25)
  Top 0.254: DMG-CPU.50 41.91,65.79 36.45,65.79 35.69,66.42 31.5,66.42 v31.5,68.58
  Bottom 0.254: XOR.5 v31.5,68.58
MA0
  Top 0.254: DMG-CPU.34 53.33,52.97 53.59,52.7 VRAM.10
MA1
  Top 0.254: DMG-CPU.35 53.39,53.77 53.59,53.98 VRAM.9
MA2
  Top 0.254: DMG-CPU.36 53.3,54.57 53.98,55.24 VRAM.8
MA3
  Top 0.254: DMG-CPU.37 52.83,55.37 53.98,56.52 VRAM.7
MA4
  Top 0.254: DMG-CPU.38 52.86,56.16 53.47,56.77 53.47,57.02 54.23,57.78 VRAM.6
MA5
  Top 0.254: DMG-CPU.39 52.64,56.96 53.09,57.4 53.09,58.67 53.47,59.05 VRAM.5
MA6
  Top 0.254: DMG-CPU.40 51.44,58.42 53.34,60.33 VRAM.4
MA7
  Top 0.254: VRAM.3 53.21,61.59 52.7,62.1 49.4,62.1 49.09,61.78 DMG-CPU.41
MA8
  Top 0.254: VRAM.25 62.99,60.33 62.23,61.09 62.23,65.28 58.04,69.47 52.2,69.47 50.16,67.44 46.61,67.44 43.5,64.33 DMG-CPU.48
MA9
  Top 0.254: VRAM.24 62.74,59.05 61.47,60.33 61.47,64.9 57.66,68.71 52.58,68.71 50.55,66.67 46.99,66.67 44.3,63.98 DMG-CPU.47
MA10
  Top 0.254: VRAM.21 61.21,55.24 59.18,57.28 59.18,63.75 56.64,66.29 53.59,66.29 51.69,64.39 48.13,64.39 46.69,62.95 DMG-CPU.44
MA11
  Top 0.254: VRAM.23 62.23,57.78 60.71,59.31 60.71,64.52 57.28,67.94 52.96,67.94 50.93,65.91 47.37,65.91 45.1,63.64 DMG-CPU.46
MA12
  Top 0.254: VRAM.2 48.9,62.87 48.29,62.26 DMG-CPU.42
MCS
  Top 0.254: VRAM.20 60.71,53.98 58.29,56.39 58.29,63.5 56.39,65.41 53.85,65.41 52.07,63.63 48.51,63.63 47.49,62.6 DMG-CPU.43
MD0
  Top 0.254: DMG-CPU.33 53.23,52.17 53.98,51.44 VRAM.11
MD1
  Top 0.254: DMG-CPU.31 53.05,50.58 53.47,50.16 VRAM.12
MD2
  Top 0.254: DMG-CPU.30 52.84,49.78 53.72,48.9 VRAM.13
MD3  (via drill 0.38)
  Top 0.254: v59.05,47.62 VRAM.15 | v49.4,49.78 49.4,49.28 49.7,48.98 DMG-CPU.29
  Bottom 0.254: v59.05,47.62 59.05,49.4 58.67,49.78 v49.4,49.78
MD4  (via drill 0.38)
  Top 0.254: v58.17,48.9 VRAM.16 | v49.46,48.19 DMG-CPU.28
  Bottom 0.254: v58.17,48.9 54.48,48.9 53.77,48.19 DMG-CPU.28 v49.46,48.19
MD5
  Top 0.254: DMG-CPU.27 53.07,47.39 53.98,46.48 56.52,46.48 57.4,47.37 57.4,49.66 57.91,50.16 VRAM.17
MD6
  Top 0.254: VRAM.18 67.18,51.44 67.94,50.67 67.94,46.99 66.8,45.85 53.72,45.85 52.98,46.59 DMG-CPU.26
MD7
  Top 0.254: VRAM.19 67.18,52.7 68.58,51.31 68.58,46.48 67.06,44.96 53.47,44.96 52.63,45.79 DMG-CPU.25
MOE
  Top 0.254: VRAM.22 61.72,56.52 59.94,58.29 59.94,64.14 56.9,67.18 53.34,67.18 51.31,65.15 47.75,65.15 45.89,63.29 DMG-CPU.45
MOSI  (1 unrouted)
MSIO  (1 unrouted)
MWR
  Top 0.254: VRAM.27 63.88,62.87 62.99,63.75 62.99,65.66 58.42,70.23 51.82,70.23 49.78,68.2 46.23,68.2 42.7,64.67 DMG-CPU.49
N$1  (1 unrouted)
N$2  (1 unrouted)
N$3
  Top 0.406: HP.1 arc90 80.01,1.91 C10.1 arc-90 78.61,6.9 78.61,12.06 arc90 77.98,12.7 77.72,12.7 arc-90 75.69,14.73 75.69,19.94 73.79,21.72 73.79,23.24 DMG-AMP.P$15 arc90 71.98,23.24 72.9,23.24
N$4
  Bottom 0.254: XOR.11 XOR.10 XOR.9
N$10  (2 unrouted)
  Top 0.254: R9.1 45.05,72.9 45.09,72.86 45.09,71.75 44.32,70.99
  Bottom 0.254: JP1.2 JP2.2 | XOR.4 32.77,68.45 36.45,68.45 XOR.1
N$13  (2 unrouted)
N$17  (1 unrouted)
N$19  (1 unrouted)
N$20  (1 unrouted)
N$21  (1 unrouted)
N$22  (1 unrouted)
N$23  (1 unrouted)
  Bottom 0.406: VR1.P$3 arc90 10.41,31.88 10.41,13.72 arc-90 10.03,13.34 arc90 6.6,9.91 6.6,8.76 arc-90 5.71,7.87 PROSOUND.1
N$24  (1 unrouted)
  Bottom 0.406: VR1.P$2 arc90 11.3,30.8 11.3,13.21 11.18,13.08 arc-90 10.54,12.45 10.41,12.45 arc90 7.49,9.53 7.49,6.86 arc-90 5.97,5.33 PROSOUND.2
N$26
  Top 0.406: HP.2 77.22,4.66 arc90 C9.1 77.18,11.6 arc90 76.83,11.94 arc-90 74.93,13.84 74.93,19.3 73.66,20.83 DMG-AMP.P$12
N$27
  Top 0.254: MIDIIN.P$2 69.68,50.01 R13.1
N$28
  Top 0.254: HP.4 72.14,5.84 arc-90 72.77,6.48 73.03,6.48 arc90 75.31,8.76 75.31,11.43 arc-90 74.17,12.57 74.17,18.41 arc90 73.91,18.67 66.55,18.67 arc-90 65.79,19.43 65.79,20.95 arc90 65.06,21.68 DMG-AMP.P$6
N$31  (2 unrouted)
N$32  (1 unrouted)
N$36  (2 unrouted)
N$37  (2 unrouted)
N$38  (2 unrouted)
N$40
  Top 0.254: R22.1 76.33,31.11 MIDIOUT.P$3
P10  (1 unrouted)
P11  (1 unrouted)
P12  (1 unrouted)
P13  (1 unrouted)
P14  (2 unrouted)
P15  (1 unrouted)
PD4  (2 unrouted)
R  (1 unrouted)
RD  (via drill 0.38, 0.38 pad 0.25)
  Top 0.254: DMG-CPU.79 26.65,46.59 26.16,46.1 26.16,45.21 27.69,43.69 v27.69,40.01 | RAM.22 33.66,25.27 33.02,24.64 32.51,24.64 31.5,23.62 v28.96,23.62
  Bottom 0.254: v27.69,40.01 27.69,39.37 28.96,38.1 v28.96,23.62 28.96,23.24 28.96,13.97 22.73,9.78 22.66,9.78 CART.4
RST  (3 unrouted)
  Top 0.406: C20.1 R1.2
RX  (3 unrouted)
S  (1 unrouted)
SCK  (2 unrouted)
SCX  (1 unrouted)
SD0
  Bottom 0.254: SCREEN.P$15 30.86,65.02 33.15,65.02 33.91,65.79 XOR.3
SD1
  Bottom 0.254: XOR.6 29.59,65.02 SCREEN.P$16
SIN  (1 unrouted)
SOUT  (1 unrouted)
SPKR  (2 unrouted)
ST  (1 unrouted)
TX  (2 unrouted)
VCC  (via drill 0.38 pad 0.25, 0.6)  (22 unrouted)
  Top 0.406: C17.1 66.04,64.16 VRAM.28 67.56,64.14 68.2,63.5 68.2,62.23 67.56,61.59 VRAM.26 v63.5,61.59
  Top 1.016: REG.4 arc-90 75.56,24.51 75.56,26.92 arc90 73.15,29.34 v69.85,29.34
  Bottom 0.254: XOR.14 XOR.13 XOR.12
  Bottom 1.016: v69.85,29.34 69.85,52.58 arc-90 66.17,56.26 66.17,60.2 arc90 64.77,61.59 v63.5,61.59 63.37,61.59 63.37,67.44
VIN  (1 unrouted)
WR  (via drill 0.38, 0.38 pad 0.25)
  Top 0.254: DMG-CPU.78 30.08,47.39 30.61,46.86 30.61,45.59 29.97,44.96 v29.97,41.15 | v28.07,22.61 33.91,22.61 33.91,20.83 34.54,20.19 37.97,20.19 40.77,22.99 42.93,22.99 42.93,24.64 40.01,24.64 RAM.27
  Bottom 0.254: CART.3 21.08,6.35 21.08,9.78 28.07,14.1 v28.07,22.61 28.07,37.97 26.92,39.12 26.92,41.15 v29.97,41.15
X0  (2 unrouted)
X1  (2 unrouted)

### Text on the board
tPlace: DMG-ROLF-01
bNames: ATMEGA | L | R | G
